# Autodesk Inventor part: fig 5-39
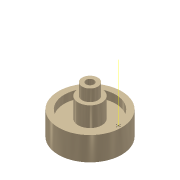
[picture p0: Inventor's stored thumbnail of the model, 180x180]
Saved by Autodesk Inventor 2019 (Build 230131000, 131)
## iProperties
Shininess: 65.0
Length Units: 11269
Angle Units: 11279
Time Units: 11290
Mass Units: 11283
Length Display Precision: 3
Angle Display Precision: 2
Created: 2001-11
Part Number: fig 5-39
Document SubType Name: Modeling
Designer: Renu Muthoo
Density: 1 g/cm^3
Material: Generic
Appearance: Metal-Titanium (Polished)
Density: 0.0
Volumn: 0.0
Area: 0.0
PropertySet Name: Model Information
Control State: 0
Master: False
Checked Out: False
Author: Renu Muthoo
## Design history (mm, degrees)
sketch "Sketch1"
  geometry: L1 (2.694, 30.112)-(5.194, 30.112); L2 (5.194, 30.112)-(5.194, 22.612); L3 (5.194, 22.612)-(7.694, 22.612); L4 (7.694, 22.612)-(7.694, 10.112); L5 (7.694, 10.112)-(16.444, 10.112); L6 (16.444, 10.112)-(16.444, 15.112); L7 (16.444, 15.112)-(20.194, 15.112); L8 (0.194, -4.034)-(0.194, 25.966); L9 (2.694, 30.112)-(2.694, 0.112); L10 (2.694, 0.112)-(20.194, 0.112); L11 (20.194, 0.112)-(20.194, 15.112)
  constraints: 22 end point, 7 parallel, 2 perpendicular, 1 horizontal
  dimensions: "d0" = 5 diameter of L9 L8; "d1" = 10 diameter of L2 L8; "d2" = 15 diameter of L4 L8; "d3" = 32.5 diameter of L6 L8; "d4" = 40 diameter of L11 L8; "d5" = 15 distance of L10.end L7.end; "d6" = 22.5 distance between parallel lines of L3 L10; "d7" = 30 distance between parallel lines of L1 L10; "d8" = 10 distance between parallel lines of L10 L5
revolve "Revolution1" sketch "Sketch1" stored, may be unused: angle "d9" = 90 deg
workaxis "Work Axis1"
sketch "Sketch2"
  geometry: 1 further point
node "Sketch3"
workaxis "Work Axis3"
body "Solid1"
